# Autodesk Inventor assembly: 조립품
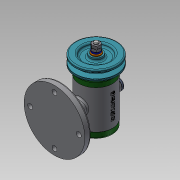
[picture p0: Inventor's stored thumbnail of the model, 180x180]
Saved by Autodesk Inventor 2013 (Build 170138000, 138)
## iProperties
Created: 2018-12
Part Number: 조립품
Document SubType Name: Assembly
Designer: Administrator
Author: Administrator
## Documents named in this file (15)
- C:\Documents and Settings\Administrator\바탕 화면\481207V1001\조립품.iam
- C:\Documents and Settings\Administrator\바탕 화면\481207V1001\V벨트풀리.ipt
- C:\Documents and Settings\Administrator\바탕 화면\481207V1001\고무캡.ipt
- C:\Documents and Settings\Administrator\바탕 화면\481207V1001\너트 M8.ipt
- 너트 M8.ipt
- C:\Documents and Settings\Administrator\바탕 화면\481207V1001\뒤커버.ipt
- C:\Documents and Settings\Administrator\바탕 화면\481207V1001\베어링 15 x 32 x 9.ipt
- C:\Documents and Settings\Administrator\바탕 화면\481207V1001\본체.ipt
- C:\Documents and Settings\Administrator\바탕 화면\481207V1001\볼트 M4 x 12.ipt
- C:\Documents and Settings\Administrator\바탕 화면\481207V1001\스프링와셔 8.ipt
- C:\Documents and Settings\Administrator\바탕 화면\481207V1001\앞커버.ipt
- C:\Documents and Settings\Administrator\바탕 화면\481207V1001\오일 실 15 25 7.ipt
- C:\Documents and Settings\Administrator\바탕 화면\481207V1001\와셔 8x17.ipt
- C:\Documents and Settings\Administrator\바탕 화면\481207V1001\축.ipt
- C:\Documents and Settings\Administrator\바탕 화면\481207V1001\키 3 x 3 x 12.ipt
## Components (2 placed, 2 different names)
1. V벨트풀리:1
2. 고무캡:1
